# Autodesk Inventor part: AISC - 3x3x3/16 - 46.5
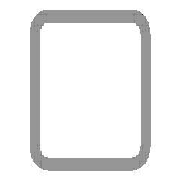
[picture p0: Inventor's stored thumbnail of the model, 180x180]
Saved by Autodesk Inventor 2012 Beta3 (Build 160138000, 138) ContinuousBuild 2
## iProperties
IsCustomPart: 1
_CCFamilyMember: 9
_CCFamilyDisplayName: ANSI AISC (Square) - Tube
_FrameMemberDoc: Frame Member File
_Version: 15.0.0
_GetPNFromCC: 1
Created: 2011-01
Part Number: AISC - 3x3x3/16 - 46.5
Material: Steel, Mild
Description: Tube
Document SubType Name: Modeling
Standard: ANSI
Designer: Beta-8540w
Standards Organization: ANSI
Language: en-US
Size Designation: 3x3x3/16
Categories: <MemberInstance><Categories><Category DisplayName="Structural Shapes" InternalName="089c4875-fa83-4c05-b084-43b9cc11f5ed" Mnemonic="GRDR"><CategoryParameter Dis
Stock Number: 3x3x3/16
Density: 7.86 g/cm^3
G_L: 46.500 in
G_W: 3.000 in
G_H: 3.000 in
+62EB5034-3A67-49DF-AD4C-C37966DAF62A+CUTDETAIL1: Notch
Author: Beta-8540w
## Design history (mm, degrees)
node "Start plane"
node "End plane"
sketch "Sketch"
  geometry: L1 (-38.1, -28.575)-(-38.1, 28.575); L2 (-28.575, 38.1)-(28.575, 38.1); L3 (38.1, 28.575)-(38.1, -28.575); L4 (28.575, -38.1)-(-28.575, -38.1); L5 (-28.575, 33.337)-(28.575, 33.338); L6 (33.338, 28.575)-(33.338, -28.575); L7 (28.575, -33.337)-(-28.575, -33.338); L8 (-33.338, -28.575)-(-33.338, 28.575); L9 (0, 56.102)-(0, -56.102) reference; L10 (-56.102, 0)-(56.102, 0) reference; A1 r 9.525 centre (-28.575, -28.575) between (-38.1, -28.575) and (-28.575, -38.1); A2 r 9.525 centre (-28.575, 28.575) between (-28.575, 38.1) and (-38.1, 28.575); A3 r 9.525 centre (28.575, 28.575) between (38.1, 28.575) and (28.575, 38.1); A4 r 9.525 centre (28.575, -28.575) between (28.575, -38.1) and (38.1, -28.575); A5 r 4.763 centre (-28.575, 28.575) between (-28.575, 33.337) and (-33.338, 28.575); A6 r 4.763 centre (28.575, 28.575) between (33.338, 28.575) and (28.575, 33.338); A7 r 4.763 centre (28.575, -28.575) between (28.575, -33.337) and (33.338, -28.575); A8 r 4.763 centre (-28.575, -28.575) between (-33.338, -28.575) and (-28.575, -33.338)
  constraints: 16 end point, 16 point on circle, 8 centre point, 8 tangent, 4 parallel, 3 equal radius, 2 perpendicular, 7 other
  dimensions: "d10" = 76.2 distance between parallel lines of L2 L4 (= G_H); "d11" = 76.2 distance between parallel lines of L1 L3 (= G_W); "d12" = 4.7625 distance between parallel lines of L3 L6 (= G_T); "d15" = 38.1 distance between parallel lines of L2 L10 (= 0.5 x d10); "d16" = 38.1 distance between parallel lines of L9 L3 (= 0.5 x d11); "d17" = 9.525 radius of A1 (= G_IR)
extrude "Body" new body sketch "Sketch" stored distance "d3" = 1181.1 (= G_L); taper "d4" = 0 deg
node "Driven Length"
  sketch "Sketch3"
    geometry: L1 (0, 0)-(10, 0) reference
    constraints: 2 end point, 1 horizontal
  workplane "Work Plane3"
  sketch "Sketch4"
    geometry: L1 (-2, 38.1)-(12, 38.1) reference; L2 (-2, 1219.2)-(12, 1219.2) reference
    dimensions: "d19" = 1181.1 distance between parallel lines of L1 L2 (derived)
workplane "Work Plane4"
split "Split1"
workplane "Work Plane5"
workplane "Work Plane6"
workplane "Work Plane7"
body "Solid1"
sketch "Sketch5"
  geometry: L1 (-38.1, -53.975)-(-38.1, 53.975); L2 (-28.575, 63.5)-(28.575, 63.5); L3 (38.1, 53.975)-(38.1, -53.975); L4 (28.575, -63.5)-(-28.575, -63.5); L5 (-28.575, 58.737)-(28.575, 58.738); L6 (33.338, 53.975)-(33.338, -53.975); L7 (28.575, -58.737)-(-28.575, -58.738); L8 (-33.338, -53.975)-(-33.338, 53.975); A1 r 9.525 centre (-28.575, -53.975) between (-38.1, -53.975) and (-28.575, -63.5); A2 r 9.525 centre (-28.575, 53.975) between (-28.575, 63.5) and (-38.1, 53.975); A3 r 9.525 centre (28.575, 53.975) between (38.1, 53.975) and (28.575, 63.5); A4 r 9.525 centre (28.575, -53.975) between (28.575, -63.5) and (38.1, -53.975); A5 r 4.763 centre (-28.575, 53.975) between (-28.575, 58.737) and (-33.338, 53.975); A6 r 4.763 centre (28.575, 53.975) between (33.338, 53.975) and (28.575, 58.738); A7 r 4.763 centre (28.575, -53.975) between (28.575, -58.737) and (33.338, -53.975); A8 r 4.763 centre (-28.575, -53.975) between (-33.338, -53.975) and (-28.575, -58.738)
  constraints: 16 end point, 16 point on circle, 8 centre point
extrude "Extrusion2" cut sketch "Sketch5" stored distance "d22" = 3.302; taper "d23" = 0 deg
other parameters: "G_W" = 76.2 [user parameter; used in 1 equation term], "G_H" = 76.2 [user parameter; used in 1 equation term], "G_T" = 4.7625 [user parameter; used in 1 equation term], "G_IR" = 9.525 [user parameter; used in 1 equation term], "G_L" = 1181.1 (= d19) [user parameter; used in 1 equation term], "G_OFFSET_START" = -38.1 [user parameter; used in 1 equation term], "G_OFFSET_END" = 0 [user parameter; used in 1 equation term], "d13" = 38.1 (= -G_OFFSET_START), "d14" = 1219.2 (= G_OFFSET_END + B_L), "B_L" = 1219.2 [user parameter; used in 1 equation term], "d18" = 90 deg
